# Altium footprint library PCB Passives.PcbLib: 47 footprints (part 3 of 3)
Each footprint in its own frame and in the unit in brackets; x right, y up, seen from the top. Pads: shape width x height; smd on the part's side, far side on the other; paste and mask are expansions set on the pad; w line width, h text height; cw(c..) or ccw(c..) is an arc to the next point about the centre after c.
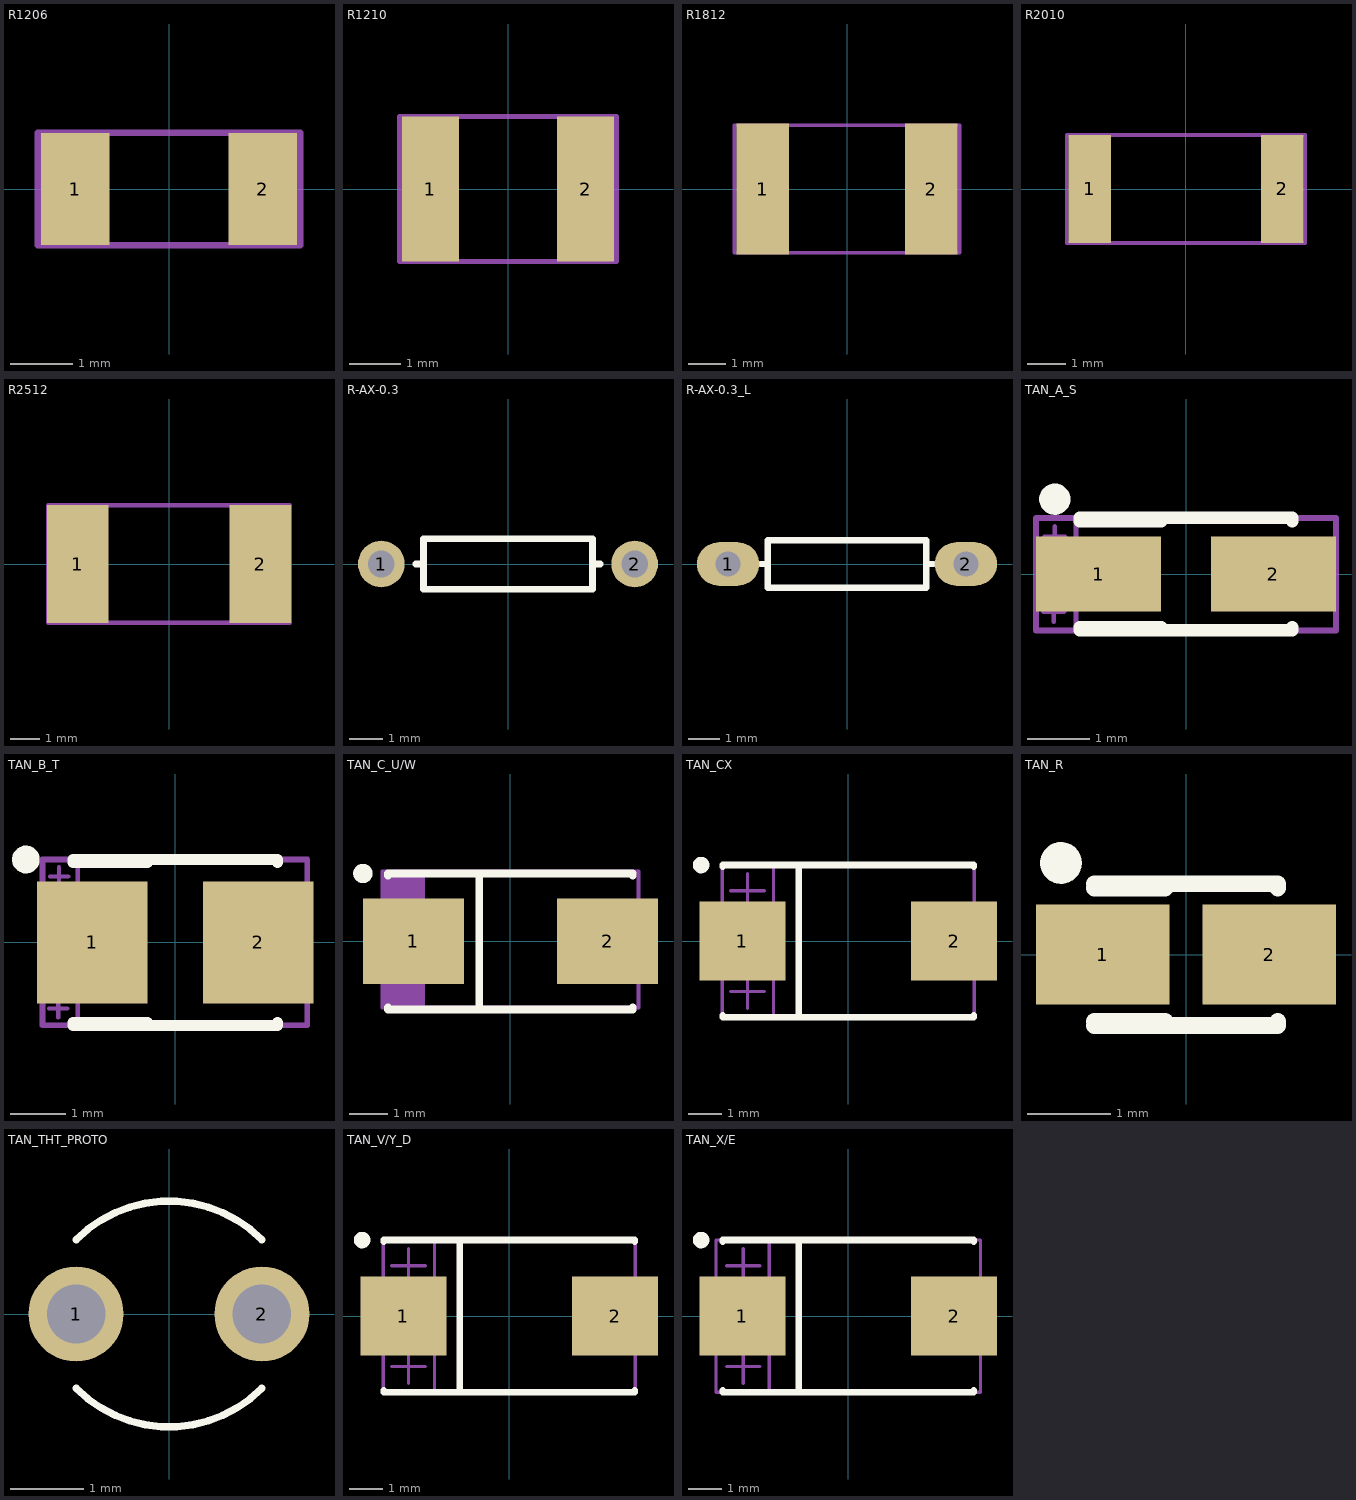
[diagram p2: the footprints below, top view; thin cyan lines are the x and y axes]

## R1206 [mm] "1206 resistor"
pads (2):
  rect 1.1x1.8 smd: 1(-1.5,0) 2(1.5,0)
Mechanical 29:
  lines w0.1: -2.1,-0.9 2.1,-0.9 2.1,0.9 -2.1,0.9 -2.1,-0.9
  text ".Designator" at -1.8,-0.3 h0.7
3D body "RES_1206.step": height 0.6, standoff 0, extent -1.6,-0.8 1.6,0.8

## R1210 [mm] "1210 resistor"
pads (2):
  rect 1.1x2.8 smd: 1(-1.5,0) 2(1.5,0)
Mechanical 29:
  lines w0.1: -2.1,-1.4 -2.1,1.4 2.1,1.4 2.1,-1.4 -2.1,-1.4
  text ".Designator" at -1.8,-0.4 h0.8
3D body "User Library-SMD RESISTOR-1(1).step": height 0.59, standoff -0.01, extent -1.6,-1.25 1.6,1.25

## R1812 [mm] "1812 resistor"
pads (2):
  rect 1.4x3.5 smd: 1(-2.25,0) 2(2.25,0)
Mechanical 29:
  lines w0.1: -3,-1.7 3,-1.7 3,1.7 -3,1.7 -3,-1.7
  text ".Designator" at -2.6,-0.4 h1
3D body "User Library-SMD RESISTOR-1(2).step": height 0.59, standoff -0.01, extent -2.25,-1.6 2.25,1.6

## R2010 [mm] "2010 resistor"
pads (2):
  rect 1.1x2.8 smd: 1(-2.5,0) 2(2.5,0)
Mechanical 29:
  lines w0.1: -3.1,-1.4 -3.1,1.4 3.1,1.4 3.1,-1.4 -3.1,-1.4
  text ".Designator" at -1.905,-0.333 h1
3D body "User Library-SMD RESISTOR-1(3).step": height 0.59, standoff -0.01, extent -2.5,-1.25 2.5,1.25

## R2512 [mm] "2512 resistor"
pads (2):
  rect 2.1x4 smd: 1(-3.1,0) 2(3.1,0)
Mechanical 29:
  lines w0.15: -4.1,-2 4.1,-2 4.1,2 -4.1,2 -4.1,-2
  text ".Designator" at -3.6,-0.6 h1.5
3D body "RES_2512.step": height 0.59, standoff -0.01, extent -3.2,-1.6 3.2,1.6

## R-AX-0.3 [mm]
pads (2):
  round 1.4 hole 0.8: 1(-3.81,0) 2(3.81,0)
Top Overlay:
  lines w0.2: -2.769,0 -2.54,0 ; 2.769,0 2.54,0 ; 2.54,0 2.54,-0.762 -2.54,-0.762 -2.54,0.762 2.54,0.762 2.54,0
3D body "Res30 0_25W SilCoat.STEP": height 2.41, standoff -2, extent -4.11,-1.2 4.11,1.2

## R-AX-0.3_L [mm] "0.3 AXIAL RESISTOR, LARGE PADS"
pads (2):
  oval 2x1.4 hole 0.8: 1(-3.81,0) 2(3.81,0)
Top Overlay:
  lines w0.2: -2.769,0 -2.54,0 ; 2.769,0 2.54,0 ; 2.54,0 2.54,-0.762 -2.54,-0.762 -2.54,0.762 2.54,0.762 2.54,0
3D body "Res30 0_25W SilCoat.STEP": height 2.41, standoff -2, extent -4.11,-1.2 4.11,1.2

## TAN_A_S [mm] "Capacitor, SM Tantalum; Body 3.2 x 1.6 mm (LxW typ)"
height 2.2
pads (2):
  rect 2x1.2 smd: 1(-1.4,0) 2(1.4,0)
Top Overlay:
  circle w0.25: c-2.1,1.2 r0.125
  lines w0.2: -1.7,-0.9 1.7,-0.9 1.7,-0.85 ; -1.7,-0.85 -0.4,-0.85 ; -1.7,0.85 -0.4,0.85 ; -1.7,0.9 1.7,0.9 1.7,0.85
Mechanical 29:
  region: -1.72,0.9 -1.8,0.9 -1.8,-0.9 -1.72,-0.9
  lines w0.076: -2.281,-0.597 -1.951,-0.597 ; -2.265,0 -1.935,0 ; -2.265,0.597 -1.935,0.597 ; -2.116,-0.762 -2.116,-0.432 ; -2.1,-0.165 -2.1,0.165 ; -2.1,0.432 -2.1,0.762
  lines w0.1: -2.4,-0.9 2.4,-0.9 2.4,0.9 -2.4,0.9 -2.4,-0.9
  text ".Designator" at -1.4,-0.4 h0.8
3D body "CAPM-TANTA-YEL.stp": height 1.8, standoff 0, extent -1.72,-0.9 1.68,0.9

## TAN_B_T [mm] "Capacitor, SM Tantalum; Body 3.5 x 2.8 mm (LxW typ)"
height 2.5
pads (2):
  rect 2x2.2 smd: 1(-1.5,0) 2(1.5,0)
Top Overlay:
  circle w0.25: c-2.7,1.5 r0.125
  lines w0.2: -1.85,-1.5 1.85,-1.5 1.85,-1.45 ; -1.85,-1.45 -0.5,-1.45 ; -1.85,1.45 -0.5,1.45 ; -1.85,1.5 1.85,1.5 1.85,1.45
Mechanical 29:
  region: -1.72,1.5 -1.8,1.5 -1.8,-1.5 -1.72,-1.5
  lines w0.076: -2.281,-1.194 -1.951,-1.194 ; -2.281,-0.597 -1.951,-0.597 ; -2.265,0 -1.935,0 ; -2.265,0.597 -1.935,0.597 ; -2.265,1.194 -1.935,1.194 ; -2.116,-1.359 -2.116,-1.029 ; -2.116,-0.762 -2.116,-0.432 ; -2.1,-0.165 -2.1,0.165 ; -2.1,0.432 -2.1,0.762 ; -2.1,1.029 -2.1,1.359
  lines w0.1: -2.4,-1.5 -2.4,-0.9 -2.4,0.9 -2.4,1.5 -2,1.5 2.388,1.5 2.388,-1.5 -2,-1.5 -2.4,-1.5
  text ".Designator" at -0.889,-0.381 h0.8
3D body "B-3528-21.STEP": height 2.11, standoff 0, extent -1.97,-1.498 1.984,1.499

## TAN_C_U/W [mm] "Capacitor, SM Tantalum; Body 6.0 x 3.2 mm (LxW typ)"
height 3.4
pads (2):
  rect 2.6x2.2 smd: 1(-2.5,0) 2(2.5,0)
Top Overlay:
  circle w0.25: c-3.8,1.75 r0.125
  lines w0.2: -3.15,-1.7 -3.15,-1.75 3.15,-1.75 3.15,-1.7 ; -3.15,1.7 -3.15,1.75 3.15,1.75 3.15,1.7 ; -0.8,-1.75 -0.8,1.75
Mechanical 29:
  region: -2.2,1.8 -3.3,1.8 -3.3,-1.7 -2.2,-1.7
  lines w0.1: -3.3,-1.7 3.3,-1.7 3.3,1.8 -3.3,1.8 -3.3,-1.7
  text ".Designator" at -1.9,-0.4 h0.8
3D body "C-6032-28.STEP": height 2.79, standoff 0, extent -3.28,-1.713 3.28,1.8

## TAN_CX [mm] "Capacitor, SM Tantalum; Body 7.3 x 4.3 mm (LxW typ)"
height 3.1
pads (2):
  rect 2.6x2.4 smd: 1(-3.2,0) 2(3.2,0)
Top Overlay:
  circle w0.25: c-4.45,2.3 r0.125
  lines w0.2: -3.8,-2.25 -3.8,-2.3 3.8,-2.3 3.8,-2.25 ; -3.8,2.25 -3.8,2.3 3.8,2.3 3.8,2.25 ; -1.5,-2.3 -1.5,2.3
Mechanical 29:
  lines w0.1: -3.556,-1.524 -2.54,-1.524 ; -3.556,0 -2.54,0 ; -3.556,1.524 -2.54,1.524 ; -3.048,-2.032 -3.048,-1.016 ; -3.048,-0.508 -3.048,0.508 ; -3.048,1.016 -3.048,2.032 ; -2.261,-2.286 -2.261,2.286 ; -3.81,-2.286 -3.81,2.286 3.81,2.286 3.81,-2.286 -3.81,-2.286
  text ".Designator" at -0.889,-0.381 h0.9
3D body "1850355.STP": height 1.85, standoff 0, extent -3.7,-2.15 3.7,2.15

## TAN_R [mm] "Capacitor, SM Tantalum; Body 2.0 x 1.25 mm (LxW typ)"
height 1.2
pads (2):
  rect 1.6x1.2 smd: 1(-1,0) 2(1,0)
Top Overlay:
  circle w0.25: c-1.5,1.1 r0.125
  lines w0.2: -1.1,-0.85 1.1,-0.85 1.1,-0.8 ; -1.1,-0.8 -0.25,-0.8 ; -1.1,0.8 -0.25,0.8 ; -1.1,0.85 1.1,0.85 1.1,0.8

## TAN_THT_PROTO [mm]
pads (2):
  round 1.3 hole 0.8: 1(-1.27,0) 2(1.27,0)
Top Overlay:
  lines w0.102: -1.27,-1.016 ccw(c0,0.254) 1.27,-1.016 ; -1.27,1.016 cw(c0,-0.254) 1.27,1.016
3D body "SW3dPS-222-0001.STEP": height 12.84, standoff -11.16, extent -2.996,-1.587 2.996,1.588

## TAN_V/Y_D [mm] "Capacitor, SM Tantalum; Body 7.3 x 4.3 mm (LxW typ)"
height 3.1
pads (2):
  rect 2.6x2.4 smd: 1(-3.2,0) 2(3.2,0)
Top Overlay:
  circle w0.25: c-4.45,2.3 r0.125
  lines w0.2: -3.8,-2.25 -3.8,-2.3 3.8,-2.3 3.8,-2.25 ; -3.8,2.25 -3.8,2.3 3.8,2.3 3.8,2.25 ; -1.5,-2.3 -1.5,2.3
Mechanical 29:
  lines w0.1: -3.556,-1.524 -2.54,-1.524 ; -3.556,0 -2.54,0 ; -3.556,1.524 -2.54,1.524 ; -3.048,-2.032 -3.048,-1.016 ; -3.048,-0.508 -3.048,0.508 ; -3.048,1.016 -3.048,2.032 ; -2.261,-2.286 -2.261,2.286 ; -3.81,-2.286 3.81,-2.286 3.81,2.286 -3.81,2.286 -3.81,-2.286
  text ".Designator" at -0.889,-0.381 h0.9
3D body "CAPM-TANTD-YEL.stp": height 3.1, standoff 0, extent -3.748,-2.25 3.752,2.25

## TAN_X/E [mm] "Capacitor, SM Tantalum; Body 7.3 x 4.3 mm (LxW typ)"
height 4.3
pads (2):
  rect 2.6x2.4 smd: 1(-3.2,0) 2(3.2,0)
Top Overlay:
  circle w0.25: c-4.45,2.3 r0.125
  lines w0.2: -3.8,-2.25 -3.8,-2.3 3.8,-2.3 3.8,-2.25 ; -3.8,2.25 -3.8,2.3 3.8,2.3 3.8,2.25 ; -1.5,-2.3 -1.5,2.3
Mechanical 29:
  lines w0.1: -3.683,-1.524 -2.667,-1.524 ; -3.683,0 -2.667,0 ; -3.683,1.524 -2.667,1.524 ; -3.175,-2.032 -3.175,-1.016 ; -3.175,-0.508 -3.175,0.508 ; -3.175,1.016 -3.175,2.032 ; -2.388,-2.286 -2.388,2.286 ; -4,-2.3 -4,2.3 4,2.3 4,-2.3 -4,-2.3
  text ".Designator" at -1.9,-0.3 h0.8
3D body "X-7343-43.STEP": height 3.91, standoff 0, extent -3.956,-2.326 3.948,2.327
